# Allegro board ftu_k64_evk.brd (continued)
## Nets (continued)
WIFI/LCD_PWR_CNTL: R153.2 U1.136(PTD7/CMT_IRO/UART0_TX/FTM0_CH7/)
N16756265: R65.1 T1.10
N16756269: R66.1 T1.15
N16757442: D11.A(1) DN2.1 J16.2 R135.2
N16757516: D10.A(1) DN1.1 J16.3 R139.2
N16758787: C93.1 U28.1(C1+)
N16758791: C93.2 U28.3(C1-)
N16758795: C92.1 U28.4(C2+)
N16758815: C92.2 U28.5(C2-)
N16758819: C91.2 U28.6(V-)
N16758823: R135.1 U28.14(T1OUT)
N16758837: R134.2 U28.11(T1IN)
N16758843: R138.2 U28.12(R1OUT)
N16758849: C89.1 U28.2(V+)
N16758873: R139.1 U28.13(R1IN)
N16759319: R25.1 U5.7(H\O\L\D\)
N16772440: D3.A(C1) R27.1 R28.2 U6.1(VOUTA)
N16775214: D4.A(C1) R31.1 R33.2 U6.7(VOUTB)
N16775930: D5.A(C1) R38.1 R40.2 U6.8(VOUTC)
N16775968: R35.2 R37.2 U6.10(VINC+)
N16775998: R39.2 R40.1 U6.9(VINC-)
N16783367: C46.2 C47.1 R45.2 R47.1 U6.12(VIND+)
N16785222: C53.2 D17.A(C1) L8.1 PT3.3 R52.2 R53.2
N16785246: PT3.1 R50.2
N16785292: C49.1 D18.A(C1) L7.1 PT3.4 R51.1 R52.1
N16786136: L8.2 R54.1
N16786139: L7.2 R49.1
N16788483: D6.A(C1) R46.1 U6.13(VIND-) U6.14(VOUTD)
N16795804: D12.A(ANODE) R157.1
N16798051: C83.1 U17.5(CSLEW)
N16806806: C77.1 R96.1 Y2.1
N16812858: R2.2 U1.68(PTA16/CMP3_IN2/SPI0_SOUT/U\A\R\)
N16812861: R4.2 U1.69(PTA17/ADC1_SE17/SPI0_SIN/U\A\R\)
N16826797: R114.2 U21.2(R\E\) U21.3(DE) U22.4(COLLECTOR)
N16826898: R118.2 U21.4(DI) U23.4(COLLECTOR)
N16826947: J12.1 R124.1
N16841183: J14.1 R132.1
N16842812: R115.1 U22.2(CATHODE)
N16843774: R119.1 U23.2(CATHODE)
N16843986: R113.2 U19.2(CATHODE)
N16846359: R113.1 U21.1(RO)
N16848477: R125.1 U26.2(CATHODE)
N16848509: R123.2 U25.2(R\E\) U25.3(DE) U26.4(COLLECTOR)
N16848511: R131.1 U27.2(CATHODE)
N16848567: R130.2 U25.4(DI) U27.4(COLLECTOR)
N16848581: R121.2 U24.2(CATHODE)
N16848643: R121.1 U25.1(RO)
N16852593: R143.2 U29.8(W\D\O\)
N16852608: C95.1 J17.1 R142.2 SW3.3(B1) SW3.4(B2) U29.1(M\R\)
N16852627: R146.1 U29.7(R\E\S\E\T\)
N16852920: R147.1 U29.6(WDI)
N16858143: P1.11(LED1-) R67.1
N16858278: P1.9(LED2-) R68.1
N16861702: R92.1 T2.10
N16861704: R93.1 T2.15
N16871213: L20.1 L22.1 Q3.2(SOURCE) R149.1
N16871247: Q5.1(GATE) R153.1 R155.1
N16871250: C100.2 Q3.1(GATE) R149.2 R151.1
N16871668: Q5.3(DRAIN) R151.2
N16872241: Q6.1(GATE) R154.1 R156.1
N16872243: C102.2 Q4.1(GATE) R150.2 R152.1
N16872250: L21.1 L23.1 Q4.2(SOURCE) R150.1
N16872280: Q6.3(DRAIN) R152.2
N16877055: R159.2 U30.1(SHDN/RT)
N16877530: R160.2 U30.8(COMP)
N16877846: C111.1 R160.1
N16878286: L25.1 U30.3(LX)
N16878713: R158.1 R161.2 U30.7(FB)
N16899253: R97.1 U12.1(BGRES)
N16906260: P2.11(LED1-) R94.1
N16913941: R84.2 U12.31(SD8/GP1)
N16913953: R85.2 U12.29(SD9/GP2)
N16913968: R86.2 U12.28(SD10/GP3)
N16913982: R87.2 U12.27(SD11/GP4)
N16913996: R89.2 U12.26(SD12/GP5)
N16917794: R11.1 U1.74(R\E\S\E\T\)
N16918817: R12.1 U1.41(EXTAL32)
N16919212: R16.2 Y1.1(OE)
N16919504: R18.1 Y1.3(CLKOUT)
N16920348: R9.1 U1.19(USB0_DP)
N16920352: R10.1 U1.20(USB0_DM)
N16922932: D8.C(CATHODE) R99.1
N16922934: Q1.3(COLLECTOR) R99.2
N16922936: Q1.1(BASE) R101.1
N16922944: Q2.3(COLLECTOR) R100.2
N16922946: D9.C(CATHODE) R100.1
N16922998: R106.1 U15.2(CATHODE)
N16923008: J8.2 R104.2 U15.4(COLLECTOR)
N16923020: J8.1 R108.1 U15.3(EMITTER)
N16923032: R105.1 U16.2(CATHODE)
N16923042: J9.2 R103.2 U16.4(COLLECTOR)
N16923054: J9.1 R107.1 U16.3(EMITTER)
N16932299: PT2.1 R41.2
N16932357: R42.2 R44.1
N16935752: C38.2 CT2.2 D14.A(C1) L6.1 R32.2
N16935822: C35.1 CT2.1 D13.A(C1) L5.1 R30.1
N16935990: L6.2 R34.1
N16935992: L5.2 R29.1
N16963015: R89.1 TP12.1(PIN1)
N16963035: R84.1 TP9.1(PIN1)
N16963490: R85.1 TP10.1(PIN1)
N16963499: R86.1 TP8.1(PIN1)
N16963508: R87.1 TP11.1(PIN1)
N16964483: J17.2 R143.1
N16992640: R13.2 U1.3(PTE2/ADC1_SE6A/SPI1_SCK/U\A\R\T)
N16997663: R140.2 U28.9(R2OUT)
N16997666: R136.2 U28.10(T2IN)
N17002202: J10.15 TP18.1(PIN1)
N17002209: J10.14 TP17.1(PIN1)
N17002232: J10.16 TP19.1(PIN1)
N17002285: J22.11 TP27.1(PIN1)
N17002298: J22.13 TP28.1(PIN1)
N17002307: J22.15 TP30.1(PIN1)
N17009409: D7.A(C1) R55.1 U7.7(OUT1)
N17012939: R137.1 U28.7(T2OUT)
N17012953: R141.1 U28.8(R2IN)
N17025356: L15.1 U20.4(VOUT)
N17038152: R14.1 U2.8(SCL)
N17038155: R15.1 U2.7(SDA)
N17041648: J21.16 TP31.1(PIN1)
N17041650: J21.14 TP29.1(PIN1)
N17041652: J21.10 TP26.1(PIN1)
N17041654: J21.2 TP25.1(PIN1)
N17042189: J22.16 R148.1
N17042264: J22.17 TP34.1(PIN1)
N17042273: J22.19 TP35.1(PIN1)
N17042288: J22.18 TP36.1(PIN1)
N17042303: J22.20 TP37.1(PIN1)
N17042405: J21.18 TP38.1(PIN1)
N17042414: J21.20 TP39.1(PIN1)
N17045351: J10.17 TP40.1(PIN1)
N17045355: J10.19 TP41.1(PIN1)
N17045369: J10.18 TP42.1(PIN1)
N17045378: J10.20 TP43.1(PIN1)
N17061950: Q2.1(BASE) R102.1
N17108951: C65.1 R65.2 R66.2
N17109053: C76.1 R92.2 R93.2
N17166355: C125.1 R75.1 R76.1
N17166431: C126.1 R77.1 R78.1
N17167419: J10.13 TP45.1(PIN1)
N17171737: TP46.1(PIN1) U1.38(DAC0_OUT/ADC0_SE23/CMP1_IN3)
N17171740: TP47.1(PIN1) U1.39(DAC1_OUT/ADC1_SE23/CMP2_IN3)
N17171751: TP48.1(PIN1) U1.35(ADC1_SE16/ADC0_SE22/CMP2_IN2)
N17171755: TP49.1(PIN1) U1.26(ADC3_DM0/ADC2_DM3/ADC1_DM1)
N167792300: PT1.1 R36.2

Pads without a net: DN1 3; DN2 3; J1 1 2; J2 1 2; J16 1 4 6 7 8 9; J18 2 3 5 11 13 17 19; NOREF#5 1; NOREF#40 1; NOREF#42 1; P1 4 5 7 8; P2 4 5 7 8; R90 1; SS1 1; T1 4 5 12 13; T2 4 5 12 13; U1 28; U2 1 3 4; U3 28; U4 1; U7 3 4 6; U10 5; U11 4; U12 19 46; U14 5; U17 4; U18 3 4; U29 5

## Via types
v1: diameter 0.61, hole 0.305, TOP to BOTTOM, 540 vias
v2: diameter 0.787, hole 0.356, TOP to BOTTOM, 2 vias

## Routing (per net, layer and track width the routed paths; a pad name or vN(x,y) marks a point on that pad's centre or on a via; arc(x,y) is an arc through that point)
AGND: length 18.3
  TOP w0.508: TVS3.2 v1(18.31,142.98) ; L18.2 v1(65.88,140.82) ; TVS5.2 v1(46.16,143.3) ; R107.2 66.15,156.96 v1(65.88,157.23) ; U21.5 v1(32.82,129.81) ; R127.1 v1(48.37,137.2) ; TVS4.1 v1(48.9,143.24) ; C88.2 v1(45.19,136.06) ; C85.2 v1(29.19,136.39) ; U25.5 v1(52.06,132.11) ; C87.1 v1(64.94,129.01) ; TVS2.1 v1(20.52,142.93) ; R117.1 v1(30.87,136.46) ; R108.2 v1(55.28,157.44)
GND: length 199.4
  TOP w0.305: U1.6 65.49,68.25 v1(65.65,68.1) ; U1.93 84.62,63.25 v1(84.42,63.45) ; U1.71 v1(83.38,52.6) ; U1.134 v1(71.38,71.54) ; v1(68.88,49.81) 68.88,46.86 69.29,46.46 C6.2 ; U1.57 76.38,52.38 v1(76.55,52.55) ; U1.107 84.9,70.25 v1(84.63,69.98) ; C20.2 63.22,42.08 63.22,45.24 v1(63.73,45.75) 66.73,48.74 v1(67.16,48.74) ; U12.5 115.11,90.37 v1(115.29,90.55) 114.96,90.87 U12.6 ; U1.44 69.88,52.42 v1(69.69,52.6) ; v1(112.42,88.24) 112.14,87.96 U12.47 ; v1(63.22,62.51) 63.46,62.75 U1.17 ; v1(108.5,88.52) 109.14,87.89 U12.41 ; U12.45 v1(111.14,88.26) ; U12.48 v1(112.64,85.62) ; v1(65.86,62.48) 65.62,62.25 U1.18 ; U1.121 v1(77.88,71.54) ; U12.33 v1(106.96,89.87) ; U12.15 v1(111.64,94.07)
  TOP w0.381: U28.15 v1(132.64,38.41)
  TOP w0.406: C106.2 v1(137.43,137.41)
  TOP w0.508: U4.3 90.79,102.43 v1(90.39,102.03) ; C64.2 114.35,72.47 v1(114.57,72.69) ; U18.2 v1(142.26,120.29) ; C22.2 v1(107.64,33.35) ; C28.2 v1(72.68,95.49) ; C101.2 v1(122.02,134.03) ; v1(112.67,130.99) 112.34,130.66 Q6.2 ; v1(138.92,112.23) C80.2 v1(138.92,114.82) ; v1(98.55,75.77) 98.22,75.44 Q2.2 ; C69.2 v1(107.79,79.61) ; C29.2 v1(93.63,94.6) ; v1(86.91,96.19) 87.15,96.43 U3.34 ; R26.1 v1(93.85,144.91) ; C70.2 v1(106.24,102.24) ; C82.2 v1(130.82,106.08) ; v1(51.94,86.46) U31.1 v1(51.94,89.87) ; C5.2 v1(58.8,70.18) ; R159.1 v1(117.3,117.82) ; v1(57.75,62.18) 58.14,62.18 C17.2 ; C18.2 v1(58.03,60.76) ; C19.2 v1(56.81,60.86) ; C95.2 v1(127.21,20.31) ; C75.2 v1(119.68,86.16) ; C72.2 118.67,93.13 C73.2 v1(119.68,93.12) ; DN2.2 v1(146.72,44.72) ; C81.2 v1(139.88,111.09) ; C104.2 v1(128.77,138.71) ; U9.2 v1(122.93,65.74) ; C126.2 v1(120.73,86.57) ; C110.2 v1(108.14,121.24) ; C78.2 v1(109.34,79.48) ; C3.2 v1(70.33,77.29) ; C2.2 v1(76.55,77.29) ; v1(57.73,65.53) 58.01,65.81 C7.2 ; R73.2 v1(119.48,69.16) ; U2.5 v1(112.6,39.59) ; R72.1 v1(149.8,10.44) ; C62.2 v1(105,65.18) ; U10.2 v1(139.43,65.7) ; C111.2 v1(121.18,118.34) ; C9.2 v1(76.27,45.31) ; C125.2 v1(120.49,94.06) ; v1(90.14,69.16) 90.44,69.47 C1.2 90.47,70.03 C8.2 v1(90.47,72.31) ; TP_GND6.1 v1(54.53,77.39) ; C31.2 v1(76.52,141.2) ; DN1.2 v1(147.51,32.36) ; C97.2 v1(115.95,20.55) ; C105.2 v1(128.74,140.33) ; C24.2 v1(100.4,51.82) ; C86.1 v1(68.85,132.03) ; C99.2 v1(101.24,140.31) ; Y1.2 v1(92.73,42.72) ; C113.2 v1(58.99,93.99) ; U3.12 76.03,95.64 v1(75.84,95.45) ; v1(145.87,21.77) 145.87,22.81 D10.C 144.57,22.68 v1(144.57,21.92) ; U17.2 v1(132.65,108.45) ; v1(100.46,44.03) BT1.1 v1(100.46,40.93) ; C63.2 v1(117.93,58.59) ; C77.2 v1(120.14,81.73) ; C89.2 v1(129.93,42.28) ; C98.2 v1(98.73,140.28) ; v1(143.35,35.13) D11.C v1(146.81,35.13) ; SW3.1 v1(130.28,16.73) ; C68.2 v1(109.46,72.56) ; C61.2 v1(119.46,58.64) ; R74.1 104.92,62.36 v1(104.72,62.15) ; C25.2 v1(98.72,51.74) ; C90.2 v1(132.47,42.3) ; TP_GND5.1 v1(93.6,107.67) ; R67.2 v1(137.37,58.08) ; L2.2 v1(30.6,102.87) ; v1(57.94,95.75) C114.2 v1(57.94,98.54) ; C67.2 v1(111.02,72.59) ; TP_GND7.1 v1(141.71,127.25) ; C26.2 v1(87.55,49.23) ; U5.4 v1(87.93,147.17) ; C27.2 98.75,47.78 v1(98.19,48.34) ; C10.2 v1(84.2,45.67) ; TP_GND8.1 v1(132.92,52.68) ; R88.1 v1(110.52,102.4) ; SW3.2 v1(130.28,7.72) ; C60.2 v1(115.92,72.67) ; C96.2 v1(127.24,22.16) ; SW1.2 v1(137.28,7.8) ; C20.2 v1(63.8,40.66) 64.25,40.21 67.92,40.21 68.57,40.86 C21.2 69.29,41.53 v1(69.7,41.94) 69.84,42.08 v1(69.84,45.44) C6.2 ; SW2.2 v1(144.32,7.85) ; C112.2 v1(59.24,85.71) ; Q5.2 v1(96.94,129.35) ; C66.1 v1(148.62,13.14) ; C91.1 v1(121.64,36.09) ; R161.1 v1(124.87,115.31) ; C74.2 v1(119.71,84.74) ; v1(104.16,75.64) 103.86,75.35 Q1.2 ; L18.1 v1(69.34,140.82) ; C4.2 v1(90.62,64.72) ; v1(99.74,91.44) 99.99,91.69 C71.2 ; C115.2 v1(50.05,95.92) ; U14.2 v1(139.03,92.86) ; C107.2 v1(125.33,111.77) ; C108.2 v1(125.27,109.91) ; C116.2 v1(50.03,99.31) ; R94.2 v1(138.62,86.17) ; C30.2 93.41,96.17 v1(93.82,95.76) ; U13.2 v1(123.21,92.99) ; C84.2 v1(130.74,115.63) ; R156.2 v1(113.09,127.57) ; SW1.1 v1(137.28,16.84) ; R155.2 v1(95.69,126.48) ; C23.2 v1(111.93,46.1) ; R97.2 v1(119.77,83.32) ; U29.3 v1(121.8,22.6) ; D12.C v1(131.13,134.7) ; U29.4 v1(121.7,23.87) ; SW2.1 v1(144.32,16.76) ; C109.2 v1(109.85,117.73)
  vias: v1(56.29,62.26) v1(56.36,65.23) v1(112.08,66.12) v1(112.06,64.36) v1(113.91,66.19) v1(113.89,64.21) v1(115.23,110.19) v1(116.17,110.21) v1(117.29,110.21) v1(132.1,149.25) v1(133.52,149.15) v1(136.93,119.33) v1(136.98,116.43) v1(137.23,149.07) v1(138.42,149.07) v1(140.58,145.67) v1(141.65,145.67)
GNDA: length 63.2
  TOP w0.305: U1.34 63.45,54.25 v1(63.24,54.46) 63.53,54.75 U1.33
  TOP w0.381: U7.5 v1(56.39,5.34)
  TOP w0.508: C32.2 v1(44.37,61.14) ; C59.2 v1(45.21,24.36) ; C48.2 v1(51.66,39.12) ; C58.2 v1(42.6,25.39) ; C39.2 37.36,61.93 v1(37.66,62.23) ; C38.1 v1(13.88,116.6) ; U32.4 v1(50.79,17.71) ; C12.2 60.35,45.06 v1(60.37,45.03) ; C57.2 46.99,22.78 v1(46.32,23.44) ; v1(55.93,35.79) TVS1.1 v1(55.93,32.63) ; C45.1 37.86,50.15 v1(38.15,50.44) ; C40.1 v1(19.86,117.7) ; D7.C v1(60.33,5.58) ; U8.1 47.13,24.9 v1(46.48,25.55) ; D16.C v1(32.99,44.53) ; C118.2 v1(42.82,10.6) ; U6.11 v1(44.27,51.64) ; v1(56.8,8.08) 57.72,8.08 C55.2 ; C54.1 v1(38.2,27.63) ; C34.2 v1(46.96,60.48) ; C13.2 v1(61.39,49.25) ; D18.C v1(26.42,34.95) ; C42.2 v1(36.09,35.36) ; L2.1 v1(30.6,99.44) ; D6.C v1(53.69,38.48) ; D15.C v1(31.89,65.77) ; C16.2 v1(57.86,54.1) ; v1(51.07,64.22) 51.75,63.54 D3.C ; C56.2 v1(51.92,25.13) ; C33.2 v1(42.81,61.02) ; C122.2 v1(41.99,14.63) ; C119.2 v1(42.09,16.48) ; D13.C v1(19.98,102.66) ; C49.2 v1(22.8,34.3) ; C47.2 v1(47.43,45.81) ; C11.2 v1(60.4,48.41) ; R163.2 v1(52.86,19.86) ; C124.2 v1(57.31,16.59) ; D5.C v1(38.77,38.51) ; D4.C v1(41.52,61.19) ; U8.2 v1(48.08,25.68) ; C43.2 v1(38.89,56.65) ; C121.2 v1(57.1,13.44) ; C53.1 v1(32.52,10.03) ; C50.2 v1(36.29,27.66) ; C120.2 v1(57.21,14.99) ; C36.2 v1(19.89,98.84) ; C117.2 v1(41.92,13.08) ; R47.2 46.16,43.72 v1(46.35,43.92) ; D17.C v1(23.6,9.93) ; C35.2 v1(14.88,98.55) ; C14.2 v1(61.31,50.8) ; D14.C v1(19.88,112.6) ; C15.2 v1(57.81,55.63)
  vias: v1(34.11,54.31) v1(34.16,51.61) v1(51.33,57.33) v1(53.01,57.3) v1(53.51,59.61) v1(55.21,55.55)
GPRS_3V3/5V: length 31.9
  TOP w0.762: C101.1 117.32,133.8 Q4.3 116.78,130.9 C102.1
  TOP w1.016: C101.1 116.69,134.44 116.69,146.33 121.58,151.23 121.58,153.59 J22.1 J22.3
P3V3_LICELL: length 9.1
  TOP w0.635: BT1.2 98.96,44.03 98.75,44.25 C27.1
  TOP w0.762: C27.1 98.97,45.86 R17.1 100.72,45.49 D2.A
VBAT: length 80.3
  TOP w0.305: U1.42 68.88,55.01 v1(69.67,55.8)
  TOP w0.508: C23.1 111.93,42.85 111.33,42.25 U2.6
  TOP w0.762: C25.1 98.75,49.43 C24.1 ; D1.C 104.8,49.63 v1(105.43,50.27) ; D1.C 102.08,49.63 101.87,49.43 C24.1 ; D1.C D2.C ; C23.1 113.08,43.56 113.81,44.3 113.81,47.8 v1(107.8,53.81) 106.47,55.14 103.03,55.14 v1(98.58,59.59) ; R17.2 100.4,47.51 C24.1
  BOTTOM w0.762: v1(98.58,59.59) 97.21,60.96 74.82,60.96 v1(69.67,55.8) ; v1(107.8,53.81) 105.43,51.44 v1(105.43,50.27)
VCC_3V3: length 1.9
  TOP w0.508: v1(47.62,94.94) L4.2 v1(47.62,93.06)
  vias: v1(51.53,93.75) v1(51.58,94.95)
VDD_3V3: length 140.3
  TOP w0.305: U1.5 60.58,68.75 C5.1 ; U1.122 77.38,73.75 77.54,73.91 C2.1 ; U1.135 70.88,74.01 71.17,74.3 C3.1 ; C8.1 87.88,71.53 87.1,70.75 U1.108 ; C9.1 76.27,49.12 75.88,49.52 U1.56 ; U11.9 109.77,65.43 109.11,64.77 107.96,64.77 C62.1 ; C6.1 69.84,50.09 69.38,50.56 U1.43 ; C69.1 108.48,82.7 108.48,83.67 109.64,84.83 U12.42 ; U1.94 89.2,63.75 C4.1
  TOP w0.406: U12.30 102.54,91.37 C71.1 ; U1.16 62.79,63.25 60.23,65.81 ; U3.11 74.06,96.43 C28.1 ; U1.70 82.88,50.29 84.2,48.97 C10.1 v1(83.46,48.18) ; v1(91.79,56.08) 91.49,56.39 R7.1 ; C70.1 106.24,98.37 107.64,96.98 U12.23 ; R120.2 v1(41.04,107.26) ; R8.1 v1(90.74,54.14) ; v1(88.62,49.28) 88.92,48.97 C26.1 ; R112.2 v1(22.73,107.87) ; C6.1 v1(70.81,47.83) ; D1.A v1(102.89,52.17)
  TOP w0.508: D9.A v1(99.16,80.14) ; R1.1 v1(74.44,45.24) ; v1(143.08,100.43) 144.96,98.55 144.96,95.59 P2.10 ; C28.1 v1(74.05,95.52) ; R6.1 R5.1 v1(91.79,59.18) ; C3.1 v1(70.28,75.92) ; R82.2 99.86,98.74 v1(99.51,98.4) ; v1(103.27,92.18) 102.71,92.18 C71.1 ; R81.2 v1(109.11,102.26) ; v1(75.33,48.26) 75.71,47.88 C9.1 ; C4.1 v1(89.25,64.74) ; R71.1 111.48,59 v1(111.15,59.33) ; v1(105.4,98.63) 105.4,98.96 C70.1 ; L20.2 v1(104.87,127.53) ; R110.1 v1(142.39,17.88) ; v1(61.39,65.81) C7.1 ; R25.2 75.62,143.73 v1(75.25,143.36) ; U29.2 125.85,21.33 C96.1 v1(125.86,22.23) ; C5.1 v1(60.17,70.13) ; v1(133.84,42.33) C90.1 133.84,40.4 134.28,39.96 U28.16 ; R80.2 v1(113.27,102.5) ; v1(108.66,65.91) 107.92,65.18 C62.1 ; R24.2 v1(92.62,143.73) ; v1(104.31,81.05) 104.06,80.8 D8.A ; U5.8 78.08,142.37 C31.1 v1(77.89,141.23) ; C1.1 88.18,70 v1(87.93,70.26) ; R57.2 v1(105.09,69.46) ; U3.33 89.75,95.64 90.79,94.6 C29.1 v1(91.41,95.4) 91.41,96.15 C30.1 90.72,96.17 v1(90.39,96.49) ; L21.2 v1(120.08,131.72) ; v1(89.56,72.49) 89.1,72.03 C8.1 ; R16.1 v1(87.57,46.51) ; R56.2 v1(105.06,66.64) ; R23.2 v1(92.77,147.61) ; U2.2 110.06,33.37 C22.1 v1(111.27,33.35) ; Y1.4 v1(88.83,46.11) ; R142.1 v1(128.42,17.73) ; C69.1 107.79,83.12 v1(107.56,83.34) ; R109.1 v1(135.38,17.6) ; R83.2 v1(99.58,88.53) ; v1(93.89,100.76) 93.89,100.45 U4.5 ; R158.2 v1(124.85,113.9) ; L11.1 v1(117.88,72.67) ; R144.1 v1(115.95,19.03) ; R58.2 v1(104.91,61) ; R145.1 v1(115.92,25.07) ; C2.1 v1(76.7,75.92) ; R111.1 v1(134.41,105.89) ; v1(47.57,88.39) L3.2 v1(47.57,90.45) ; R79.2 v1(111.91,102.39)
  vias: v1(102.66,114.6) v1(102.66,113.33) v1(102.66,112.37) v1(102.69,111.25)
VDD_5V: length 75.5
  TOP w1.016: v1(54.6,66.98) 55.09,66.49 55.09,59.46 55.98,58.57 C19.1 58.71,58.57 R3.2 ; v1(54.66,71.02) 54.66,71.75 61.37,78.46 61.37,87.9 60.48,88.79 C112.1
  BOTTOM w1.016: v1(54.66,71.02) 54.6,70.97 v1(54.6,66.98)
  BOTTOM w1.524: v1(70.56,126.9) v1(71.65,127.99) 76.3,132.64 v2(103.96,132.64) v1(105.69,132.64)
VDDA_2V5: length 53.3
  TOP w0.305: C73.1 116.55,92.37 U12.9 ; U12.2 114.98,88.87 115.21,88.65 115.21,87.83 116.4,86.64 116.82,86.64 C75.1
  TOP w0.508: v1(125.57,89.53) 125.58,89.55 125.58,92.78 125.37,92.99 U13.5
  TOP w0.762: v1(116.14,84.74) C74.1 117.32,86.14 C75.1 ; v1(128.44,95.86) 128.42,95.89 T2.2 ; T2.7 v1(125.57,89.53) ; C73.1 117.3,93.13 C72.1 117.3,95.18 118,95.89 v1(118.82,95.89)
  BOTTOM w0.762: v1(116.14,84.74) 114.45,86.44 114.45,90.9 118.82,95.27 v1(118.82,95.89) 119.48,96.55 127.76,96.55 v1(128.44,95.86) 128.44,92.41 v1(125.57,89.53)
VDDA_3V3: length 25.6
  TOP w0.305: U1.31 60.37,55.75 C15.1
  TOP w0.508: v1(61.31,52.63) 61.08,52.4 L1.2 ; v1(61.21,54.1) C16.1 60.27,55.6 C15.1 ; U7.8 v1(55.35,8.19) ; U6.4 44.27,58.62 C32.1 v1(45.3,58.72) ; U8.3 49.03,23.07 C57.1 v1(49.99,22.78) ; v1(52.08,26.5) C56.1 50.23,27.24 U8.4 ; U32.8 45.07,13.9 C117.1 45.09,13.08 v1(45.5,12.67) ; C33.1 v1(42.81,57.74) ; C118.1 v1(45.45,11.56)
  vias: v1(36.85,65.94) v1(37.92,66.01) v1(38.93,66.04) v1(49.42,54.71) v1(49.47,55.91) v1(52.22,51.97) v1(53.08,52.78)
VDDCR_1.2V: length 4.9
  TOP w0.127: U11.6 111.79,69.39 C67.1 110.96,70.21 C68.1
WIFI/LCD_3V3/5V: length 35.9
  TOP w1.016: J21.1 J21.3 J21.5 ; C100.1 99.37,132.13 Q3.3 101.4,135.27 C99.1 98.73,135.43 C98.1 98.71,135.41 98.22,135.41 v2(96.93,136.7)
  BOTTOM w1.016: v2(96.93,136.7) 96.93,150.41 J21.1
ADC_S1: length 12.5
  TOP w0.127: TP4.1 91.99,53.62 89.3,53.62 87.93,54.99 87.93,55.27 86.45,56.75 U1.80
ADC_S2: length 11.5
  TOP w0.127: U1.79 86.45,56.25 87.55,55.15 87.55,55.01 89.19,53.37 93.87,53.37 TP3.1
ADC_S3: length 10.9
  TOP w0.127: TP2.1 94.91,53.11 89.09,53.11 86.45,55.75 U1.78
ADC_S4: length 11.7
  TOP w0.127: TP1.1 92.7,52.86 88.84,52.86 86.45,55.25 U1.77
DC_A1_OUT: length 53
  TOP w0.305: U1.59 77.38,49.98 v1(77.4,49.96) ; R55.2 59.39,7.78 C55.1 59.25,8.08 v1(59.25,8.94)
  BOTTOM w0.305: v1(59.25,8.94) 78.05,27.74 78.05,49.35 77.44,49.96 v1(77.4,49.96)
DC_IN: length 8.5
  TOP w0.508: J6.1 44.92,9.54 R48.1 49.78,7.33 49.78,7.29 U7.1
DC_OUT: length 8.4
  TOP w0.508: U7.2 50.05,6.64 48.07,4.66 R48.2 44.92,4.66 J6.2
DC_V1_OUT: length 32.8
  TOP w0.305: R46.2 51.66,43.56 ; 51.66,43.56 51.84,43.74 v1(52.8,43.74) ; 51.66,43.56 C48.1 ; v1(77.44,49.1) 78.01,49.67 78.01,50.21 77.88,50.34 U1.60
  BOTTOM w0.305: v1(52.8,43.74) 72.08,43.74 v1(77.44,49.1)
DEBUG_RX: length 113.1
  TOP w0.127: R138.1 140.25,33.86 v1(140.08,34.04) ; U1.51 73.38,50.4 73.13,50.15 73.13,20.4 80.58,12.95 106.67,12.95 v1(106.93,12.69)
  BOTTOM w0.127: v1(106.93,12.69) 107.28,12.69 109.12,14.53 123.99,14.53 140.08,30.61 v1(140.08,34.04)
DEBUG_TX: length 111.5
  TOP w0.127: v1(107.9,12.57) 107.87,12.57 107.24,13.21 80.69,13.21 73.41,20.49 73.41,49.56 73.88,50.03 U1.52 ; v1(141.35,31.52) 141.25,31.62 140.3,31.62 R134.1
  BOTTOM w0.127: v1(107.9,12.57) 107.9,12.95 109,14.05 123.87,14.05 v1(141.35,31.52)
DM9000_INT#: length 40
  TOP w0.127: U1.137 69.88,71.21 70.89,70.21 73.76,70.21 v1(74.01,70.46) ; v1(100.3,86.25) 100.27,86.27 100.27,86.83 R95.2
  BOTTOM w0.127: v1(100.3,86.25) 99.68,86.25 86.4,72.97 76.63,72.97 74.11,70.46 v1(74.01,70.46)
DM9000_WAKE: length 99.2
  TOP w0.127: R91.1 107.75,102.56 107.29,103.02 101.02,103.02 97.54,99.54 97.54,90.78 v1(97.79,90.53) ; v1(87.25,51.13) 87.25,51.83 U1.73 ; v1(97.26,88.67) 97.03,88.44 97.03,85.04 98.27,83.79 v1(104.17,83.79)
  BOTTOM w0.127: v1(97.79,90.53) 97.79,89.2 v1(97.26,88.67) ; v1(87.25,51.13) 89.61,51.13 91.25,49.49 106.99,49.49 112.86,55.36 112.86,66.89 111.63,68.12 111.63,73.3 105.99,78.94 105.99,81.97 v1(104.17,83.79)
DM_INT: length 5.2
  TOP w0.127: R95.1 102.22,87.18 R83.1 103.34,88.53 104.17,89.37 U12.34
DM_LED1: length 69.5
  TOP w0.127: P2.9 148.46,94.38 148.46,85.32 147.11,83.97 145.92,83.97 137.61,75.67 108.81,75.67 105.25,79.22 105.25,82.97 108.14,85.85 U12.39
DM_LED2: length 54.9
  TOP w0.127: U12.38 107.64,85.71 105,83.07 105,79.12 108.7,75.41 139.09,75.41 P2.12
EECLK: length 7.5
  TOP w0.127: R80.1 112.27,98.76 110,98.76 109.14,97.89 U12.20
EECS: length 6.7
  TOP w0.127: R79.1 111.17,99.01 109.54,99.01 108.64,98.1 U12.21
ENET1_RX+: length 26.5
  TOP w0.127: U11.23 116.01,65.93 v1(116.44,66.36) 116.95,66.87 R59.2 ; T1.6 127.5,63.65 128.14,63.02 128.14,62.56 128.8,61.9 128.8,60.31 128.08,59.59 125.22,59.59 123.01,61.8 123.01,64.66 122.88,64.79 U9.3 121.83,64.27 122.09,64.01 v1(122.22,64.01)
  BOTTOM w0.127: v1(122.22,64.01) 121.8,64.01 119.62,66.19 116.61,66.19 v1(116.44,66.36)
ENET1_RX-: length 26.5
  TOP w0.127: v1(123.77,63.86) 124.18,63.86 124.47,64.15 U9.4 123.41,64.79 123.29,64.66 123.29,61.91 125.33,59.87 127.96,59.87 128.52,60.43 128.52,61.77 128.38,61.91 128.12,61.91 127.99,61.77 127.99,61.57 127.53,61.11 T1.8 ; U11.22 116.2,65.43 116.29,65.52 v1(116.58,65.52) R60.2
  BOTTOM w0.127: v1(123.77,63.86) 123.4,63.49 121.93,63.49 119.5,65.91 116.97,65.91 v1(116.58,65.52)
ENET1_TX+: length 25.3
  TOP w0.127: R61.2 117.56,63.91 116.94,63.91 v1(116.47,64.38) 116.06,64.38 115.51,64.93 U11.21 ; v1(122.04,67.44) 121.83,67.22 U9.1 122.88,66.69 123.01,66.81 123.01,68.39 123.4,68.78 125.67,68.78 125.95,69.06 125.95,69.6 126.36,70 T1.1
  BOTTOM w0.127: v1(116.47,64.38) 116.13,64.38 115.79,64.71 115.79,67.18 116.89,68.28 123.03,68.28 123.24,68.07 123.24,67.46 122.96,67.18 122.3,67.18 v1(122.04,67.44)
ENET1_TX-: length 25.5
  TOP w0.127: R62.2 117.18,63.51 v1(116.36,63.51) 115.45,64.43 U11.20 ; v1(124.23,67.49) 124.47,67.25 U9.6 123.41,66.69 123.29,66.81 123.29,68.28 123.51,68.5 125.55,68.5 126.59,67.46 T1.3
  BOTTOM w0.127: v1(124.23,67.49) 123.72,67.49 123.51,67.69 123.51,68.19 123.15,68.55 116.77,68.55 115.51,67.3 115.51,64.59 116.36,63.74 v1(116.36,63.51)
ENET2_RX+: length 29.5
  TOP w0.127: T2.6 127.48,90.81 128.19,90.09 128.19,89.65 128.91,88.93 128.91,86.94 128.3,86.33 124.47,86.33 123.08,87.72 123.08,91.8 122.84,92.04 U13.3 122,91.22 v1(122.37,90.86) ; R77.2 116.92,87.57 v1(116.07,88.42) 115.12,89.37 U12.3
  BOTTOM w0.127: v1(116.07,88.42) 116.35,88.7 119.77,88.7 121.93,90.86 v1(122.37,90.86)
ENET2_RX-: length 29.2
  TOP w0.127: R78.2 116.36,88.92 v1(116.07,89.2) 115.52,89.76 115.01,89.76 114.9,89.87 U12.4 ; T2.8 127.45,88.27 128.21,89.03 128.42,89.03 128.63,88.81 128.63,87.06 128.19,86.61 124.58,86.61 123.36,87.83 123.36,91.74 123.66,92.04 U13.4 124.65,91.53 v1(124.07,90.96)
  BOTTOM w0.127: v1(116.07,89.2) 116.3,88.98 119.65,88.98 122.05,91.38 123.65,91.38 v1(124.07,90.96)
ENET2_TX+: length 19.6
  TOP w0.127: U12.7 115.2,91.37 v1(116.1,90.47) 116.29,90.29 R75.2 ; T2.1 126.44,97.16 125.52,96.24 123.75,96.24 123.18,95.67 123.18,94.07 123.06,93.94 U13.1 v1(122,94.75)
  BOTTOM w0.127: v1(116.1,90.47) 120.62,95 121.76,95 v1(122,94.75)
ENET2_TX-: length 21.6
  TOP w0.127: T2.3 126.54,94.61 125.19,95.96 123.87,95.96 123.46,95.55 123.46,94.07 123.59,93.94 U13.6 124.65,94.78 v1(124.4,95.02) ; U12.8 115.18,91.87 115.72,91.34 v1(116.17,91.34) 116.95,91.34 R76.2
  BOTTOM w0.127: v1(116.17,91.34) 116.57,91.34 120.5,95.28 124.15,95.28 v1(124.4,95.02)
ENET_3V3A: length 110
  TOP w0.305: U11.1 114.29,68.99 114.35,69.05 C64.1 ; C63.1 117.4,61.03 116.45,61.98 116.45,62.47 U11.19
  TOP w0.508: U9.5 125.22,65.74 125.47,65.48 v1(125.47,62.76) 125.85,62.38 T1.7
  TOP w0.762: P1.10 146.31,67.74 142.23,71.82 130.36,71.82 129.31,70.76 129.31,69.14 v1(128.9,68.73) T1.2 ; v1(125.9,71.73) 121.48,71.73 119.97,70.22 ; 119.97,70.22 L11.2 117.85,70.19 C60.1 115.9,70.21 C64.1 ; 119.97,70.22 120.87,69.32 120.87,67.39 120.36,66.87 R59.1 119.43,66.86 R60.1 R61.1 119.48,64.13 R62.1 119.46,62.8 C61.1 C63.1 ; v1(124.23,74.63) 107.13,74.63 102.1,69.6 102.1,65.13 103.5,63.73 R70.2
  BOTTOM w0.762: v1(125.47,62.76) 126.28,62.76 128.9,65.38 v1(128.9,68.73) v1(125.9,71.73) 124.23,73.41 v1(124.23,74.63)
ETH1_RXN: length 36
  TOP w0.127: v1(138.6,63.86) 138.53,63.86 138.26,64.12 U10.3 139.54,64.75 139.75,64.54 139.75,63.66 140.43,62.98 141.36,62.98 141.88,62.46 141.88,60.63 140.89,59.64 134.77,59.64 133.88,60.53 133.88,61.62 134.11,61.85 134.39,61.85 135.12,61.11 T1.9
  BOTTOM w0.127: P1.6 150.37,61.9 141.38,61.9 140.22,63.07 140.22,64.43 139.9,64.74 138.45,64.74 138.26,64.55 138.26,64.12 138.53,63.86 v1(138.6,63.86)
ETH1_RXP: length 36
  TOP w0.127: T1.11 135.05,63.65 134.41,63.02 134.41,62.55 133.6,61.74 133.6,60.41 134.65,59.36 141,59.36 142.16,60.51 142.16,62.59 141.49,63.26 140.55,63.26 140.02,63.78 140.02,64.62 140.33,64.92 140.73,64.92 U10.4 140.9,64.05 v1(140.74,63.88)
  BOTTOM w0.127: P1.3 152.9,63.62 151.47,62.18 141.5,62.18 140.74,62.94 v1(140.74,63.88)
ETH1_TXN: length 34.5
  TOP w0.127: v1(140.87,67.46) 140.9,67.43 U10.6 139.87,66.65 139.59,66.93 139.59,67.75 140.04,68.2 141.82,68.2 142.36,68.74 142.36,69.99 141.36,70.99 134.19,70.99 133.7,70.5 133.7,69.35 134.01,69.04 134.3,69.04 134.39,68.96 134.39,68.28 135.2,67.46 T1.14
  BOTTOM w0.127: v1(140.87,67.46) 140.81,67.41 140.18,67.41 140,67.59 140,67.84 140.18,68.02 142.36,68.02 144.42,65.96 150.38,65.96 P1.2
ETH1_TXP: length 34.4
  TOP w0.127: T1.16 135.05,70 134.39,69.34 134.11,69.34 133.98,69.47 133.98,70.36 134.31,70.69 134.31,70.71 141.24,70.71 142.08,69.88 142.08,68.86 141.7,68.48 139.92,68.48 139.31,67.87 139.31,66.93 139.04,66.65 U10.1 138.26,67.3 v1(138.42,67.46)
  BOTTOM w0.127: P1.1 144.53,66.24 142.47,68.3 140.06,68.3 139.72,67.96 139.72,67.67 139.52,67.46 v1(138.42,67.46)
ETH2_RXN: length 34.3
  TOP w0.127: v1(138.01,91.2) U14.3 138.92,91.91 139.14,91.69 139.14,90.66 139.43,90.37 141.69,90.37 142.41,89.65 142.41,88.51 142.22,88.32 137.83,88.32 136.73,87.22 134.51,87.22 133.93,87.81 133.93,88.75 134.01,88.82 134.39,88.82 134.94,88.27 T2.9
  BOTTOM w0.127: v1(138.01,91.2) 138.9,91.2 139.95,90.14 148.41,90.14 149.42,89.13 150.13,89.13 P2.6
ETH2_RXP: length 38.9
  TOP w0.127: v1(140.65,91.25) U14.4 139.63,91.91 139.42,91.69 139.42,90.78 139.54,90.65 141.8,90.65 142.69,89.76 142.69,88.39 142.34,88.04 137.94,88.04 136.85,86.94 134.4,86.94 133.65,87.69 133.65,88.86 133.91,89.12 134.25,89.12 134.36,89.23 134.36,90.14 135.02,90.81 T2.11
  BOTTOM w0.127: P2.3 152.59,90.72 152.59,90.03 151.62,89.05 150.61,89.05 150.25,89.41 149.54,89.41 148.52,90.42 140.07,90.42 139.63,90.86 139.63,91.04 139.83,91.25 v1(140.65,91.25)
ETH2_TXN: length 30.9
  TOP w0.127: v1(139.67,94.42) 140.28,93.81 U14.6 140.76,93.81 142.03,95.08 142.03,96.76 140.65,98.15 134.07,98.15 133.7,97.78 133.7,97.01 134.27,96.44 134.27,95.16 134.82,94.61 T2.14
  BOTTOM w0.127: v1(139.67,94.42) 139.91,94.67 141.2,94.67 143.31,92.56 150.62,92.56 151.04,92.13 P2.2
ETH2_TXP: length 31.7
  TOP w0.127: U14.1 138.33,93.81 138.65,94.13 138.65,94.31 v1(138.87,94.52) 139.29,94.95 141.5,94.95 141.75,95.2 141.75,96.65 140.53,97.87 134.26,97.87 133.98,97.59 133.98,97.13 134.23,96.88 135.2,96.88 T2.16
  BOTTOM w0.127: v1(138.87,94.52) 139.29,94.95 141.32,94.95 143.43,92.84 150.57,92.84 150.88,93.15 P2.1
EXT_5V: length 60.1
  TOP w0.508: L17.1 v1(61.39,128.45)
  BOTTOM w0.508: v1(61.39,128.45) 61.39,145.41 54.2,152.6 26.38,152.6 J13.1
EXTAL: length 48.6
  TOP w0.127: v1(84.27,50.15) 84.27,50.32 83.88,50.71 U1.72 ; v1(112.31,68.17) 112.31,67.16 U11.5 ; R18.2 v1(90.53,49.24)
  BOTTOM w0.127: v1(112.31,68.17) 113.11,67.37 113.11,55.26 107.09,49.24 v1(90.53,49.24) 89.28,50.5 84.62,50.5 v1(84.27,50.15)
EZP_CS: length 3.5
  TOP w0.127: R1.2 74.44,49.07 74.88,49.51 U1.54
FB_AD0: length 56.9
  TOP w0.127: U4.2 92.33,101.96 91.6,101.23 U3.40 86.98,101.23 v1(86.94,101.27) ; U1.133 71.88,73.86 72.12,74.11 72.12,77.76 68.19,81.69 68.19,99.9 70.23,101.94 71.94,101.94 v1(72.46,101.42)
  BOTTOM w0.127: v1(86.94,101.27) 84.5,103.71 74.75,103.71 v1(72.46,101.42)
FB_AD0_N: length 3.2
  TOP w0.127: U3.39 90.78,100.43 U4.4
FB_AD1: length 84.5
  TOP w0.127: U12.32 104.64,90.37 103.75,89.48 99.54,89.48 98.96,88.91 98.15,88.91 97.1,89.97 97.1,103.34 95.38,105.05 79.12,105.05 v1(78.53,104.47) 78.49,104.43 U3.1 ; v1(71.52,101.42) 70.07,101.42 68.45,99.8 68.45,82.07 72.38,78.14 U1.132
  BOTTOM w0.127: v1(78.53,104.47) 74.57,104.47 v1(71.52,101.42)
FB_AD2: length 43.2
  TOP w0.127: v1(79.34,102.62) 79.29,102.62 78.28,103.63 U3.2 ; v1(69.87,100.48) 68.7,99.31 68.7,82.52 72.88,78.34 U1.131
  BOTTOM w0.127: v1(79.34,102.62) 78.85,103.11 75.7,103.11 73.21,100.62 70.01,100.62 v1(69.87,100.48)
FB_AD3: length 40.9
  TOP w0.127: v1(71.28,99.96) 69.76,99.96 68.96,99.16 68.96,82.97 73.38,78.55 U1.130 ; v1(78.58,102.59) 78.34,102.83 U3.3
  BOTTOM w0.127: v1(78.58,102.59) 75.84,102.59 73.02,99.77 71.47,99.77 v1(71.28,99.96)
FB_AD4: length 37.4
  TOP w0.127: v1(69.97,99.44) 69.21,98.68 69.21,83.43 73.88,78.76 U1.129 ; v1(75.89,101.9) 76.02,102.03 U3.4
  BOTTOM w0.127: v1(75.89,101.9) 73.43,99.44 v1(69.97,99.44)
FB_AD5: length 48
  TOP w0.127: v1(71.17,88.27) 70.73,88.7 70.73,97.22 74.74,101.23 U3.5 ; v1(74.37,88.28) 74.37,87.71 76.57,85.51 79.83,85.51 80.03,85.72 80.03,88.82 80.23,89.03 80.67,89.03 80.88,88.82 U1.115
  BOTTOM w0.127: v1(74.37,88.28) 74.35,88.27 v1(71.17,88.27)
FB_AD6: length 31.9
  TOP w0.127: U3.18 75.98,90.84 74.89,89.76 74.89,87.55 76.57,85.87 79.55,85.87 79.75,86.07 79.75,89.08 79.95,89.28 81.17,89.28 81.38,89.08 U1.114
FB_AD7: length 30.4
  TOP w0.127: U3.19 76.65,90.04 75.59,88.98 75.59,87.21 76.49,86.3 79.29,86.3 79.5,86.51 79.5,89.38 79.7,89.59 81.67,89.59 81.88,89.38 U1.113
FB_AD8: length 30.1
  TOP w0.127: U1.112 82.38,89.76 82.17,89.97 79.45,89.97 79.24,89.76 79.24,86.88 79.04,86.67 76.48,86.67 75.84,87.32 75.84,88.77 76.31,89.24 U3.20
FB_AD9: length 29.3
  TOP w0.127: U1.111 82.88,90.07 82.67,90.27 79.19,90.27 78.99,90.07 78.99,87.25 78.79,87.05 76.47,87.05 76.09,87.42 76.09,87.88 76.65,88.44 U3.21
FB_AD10: length 26.7
  TOP w0.127: U1.110 83.38,90.47 83.17,90.68 78.94,90.68 78.73,90.47 78.73,87.85 78.53,87.64 U3.22
FB_AD11: length 17.8
  TOP w0.127: U1.109 83.88,84.62 86.9,87.64 U3.23
FB_AD12: length 28.1
  TOP w0.127: U3.24 89.89,88.44 90.18,88.15 90.18,87.31 89.06,86.19 89.06,74.5 91.23,72.33 91.23,69.17 90.65,68.59 87.31,68.59 86.65,69.25 U1.105
FB_AD13: length 29.2
  TOP w0.127: U1.104 86.56,68.75 86.97,68.34 90.76,68.34 91.49,69.07 91.49,72.44 89.31,74.61 89.31,86.09 90.43,87.21 90.43,88.46 89.64,89.24 U3.25
FB_AD14: length 30.3
  TOP w0.127: U1.103 86.51,68.25 86.68,68.08 90.86,68.08 91.74,68.96 91.74,72.54 89.57,74.72 89.57,85.98 90.68,87.1 90.68,88.77 89.42,90.04 U3.26
FB_AD15: length 36.6
  TOP w0.127: U1.97 86.79,65.25 87.52,65.99 90.93,65.99 93.26,68.33 93.26,73.18 92.17,74.27 92.17,83.13 v1(92.55,83.52) ; v1(90.09,83.52) 90.09,85.52 91.21,86.64 91.21,89.26 89.62,90.84 U3.27
  BOTTOM w0.127: v1(90.09,83.52) v1(92.55,83.52)
FB_AD16: length 53.5
  TOP w0.127: U1.96 86.95,64.75 87.93,65.74 91.03,65.74 93.52,68.22 93.52,73.28 92.43,74.38 92.43,81.85 95.98,85.4 95.98,102.18 94.51,103.66 90.75,103.66 89.92,102.83 U3.42
FB_AD17: length 54.2
  TOP w0.127: U1.95 87.16,64.25 88.39,65.48 91.14,65.48 93.77,68.11 93.77,73.39 92.68,74.48 92.68,81.74 96.24,85.3 96.24,102.29 94.61,103.91 89.43,103.91 89.15,103.63 U3.43
FB_AD18: length 57.8
  TOP w0.127: U1.92 91.6,62.75 94.03,65.18 94.03,73.49 92.93,74.59 92.93,80.8 96.62,84.48 96.62,103.02 95.21,104.43 U3.44
FB_AD24: length 75.4
  TOP w0.127: v1(89.96,92.41) 89.92,92.44 U3.29 82.96,92.44 82.18,93.23 82.18,96.15 78.7,99.63 U3.7 73.5,99.63 70.99,97.12 70.99,89.29 78.38,81.9 U1.120 ; v1(109.66,96.79) 109.76,96.79 110.14,96.41 U12.18
  BOTTOM w0.127: v1(89.96,92.41) 90.94,93.38 95.02,93.38 98.43,96.79 v1(109.66,96.79)
FB_AD25: length 78.2
  TOP w0.127: v1(90.72,92.41) 90.72,92.58 90.06,93.24 U3.30 ; v1(82.57,92.02) 81.92,92.67 81.92,95.24 78.33,98.83 U3.8 73.06,98.83 71.24,97.01 71.24,89.4 78.88,81.76 U1.119 ; U12.17 110.64,96.64 v1(110.54,96.75)
  BOTTOM w0.127: v1(110.54,96.75) 110,96.22 98.22,96.22 95.13,93.13 91.45,93.13 v1(90.72,92.41) 90.11,91.8 82.8,91.8 v1(82.57,92.02)
FB_AD26: length 79.6
  TOP w0.127: v1(91.49,92.41) 89.85,94.04 U3.31 ; v1(81.81,92.05) 81.67,92.19 81.67,95.02 78.66,98.03 U3.9 72.62,98.03 71.5,96.9 71.5,89.5 79.38,81.62 U1.118 ; U12.16 111.14,96.31 111.3,96.47 v1(111.3,96.75)
  BOTTOM w0.127: v1(111.3,96.75) 110.38,95.83 98.37,95.83 95.42,92.88 91.96,92.88 v1(91.49,92.41) 90.37,91.29 82.57,91.29 v1(81.81,92.05)
FB_AD27: length 81.3
  TOP w0.127: U1.117 79.88,81.48 71.75,89.61 71.75,96.8 72.18,97.23 U3.10 78.99,97.23 81.05,95.17 v1(81.05,92.08) ; U3.32 89.78,94.84 92.25,92.38 v1(92.25,92.35) ; v1(112.26,96.75) 112.14,96.63 U12.14
  BOTTOM w0.127: v1(112.26,96.75) 110.87,95.35 98.42,95.35 95.42,92.35 v1(92.25,92.35) 90.77,90.88 82.24,90.88 81.05,92.07 v1(81.05,92.08)
FB_AD28: length 88
  TOP w0.127: U1.102 90.89,67.75 91.99,68.85 91.99,72.65 90.9,73.74 90.9,85.55 94.71,89.36 94.71,95.63 93.11,97.23 U3.35 86.89,97.23 v1(86.76,97.1) ; U3.13 78.76,94.84 v1(79.52,94.08) ; v1(114.32,96.9) 114.37,96.85 114.37,95.94 113.76,95.33 U12.13
  BOTTOM w0.127: v1(114.32,96.9) 111.98,99.24 90.93,99.24 88.79,97.1 v1(86.76,97.1) 81.71,97.1 79.52,94.92 v1(79.52,94.08)
FB_AD29: length 91
  TOP w0.127: v1(115.08,96.82) 115.08,94.07 114.88,93.87 U12.12 ; v1(78.73,94.04) U3.14 ; v1(86.99,97.94) 87.08,98.03 U3.36 90.15,98.03 90.51,97.68 93.53,97.68 94.97,96.24 94.97,89.25 91.16,85.44 91.16,73.85 92.25,72.75 92.25,68.75 90.75,67.25 U1.101
  BOTTOM w0.127: v1(115.08,96.82) 115.08,97.33 112.92,99.49 90.09,99.49 88.54,97.94 v1(86.99,97.94) 81.91,97.94 78.73,94.77 v1(78.73,94.04)
FB_AD30: length 96.8
  TOP w0.127: v1(87.02,98.78) 87.07,98.83 U3.37 89.71,98.83 90.61,97.93 93.64,97.93 95.22,96.35 95.22,89.15 91.41,85.34 91.41,73.95 92.5,72.86 92.5,68.64 90.61,66.75 U1.100 ; U12.11 115.09,93.37 115.83,94.11 115.83,96.73 v1(115.84,96.75) ; U3.15 75.86,93.24 v1(75.81,93.29)
  BOTTOM w0.127: v1(115.84,96.75) 115.84,97.13 113.22,99.75 88.29,99.75 87.32,98.78 v1(87.02,98.78) 81.3,98.78 v1(75.81,93.29)
FB_AD31: length 101.5
  TOP w0.127: U12.10 115.3,92.87 116.62,94.19 116.62,96.71 v1(116.6,96.72) ; v1(75.79,92.53) 75.88,92.44 U3.16 ; v1(86.99,99.57) 87.05,99.63 U3.38 89.69,99.63 91,98.32 93.6,98.32 95.47,96.45 95.47,89.04 91.66,85.23 91.66,74.06 92.76,72.97 92.76,68.54 90.72,66.5 87.06,66.5 86.81,66.25 U1.99
  BOTTOM w0.127: v1(75.79,92.53) 75.25,93.07 75.25,93.7 81.12,99.57 v1(86.99,99.57) 87.42,100 113.33,100 v1(116.6,96.72)
FB_CS0_N: length 36.3
  TOP w0.127: U3.6 75.94,100.43 v1(75.74,100.23) ; U1.128 74.38,73.6 74.13,73.84 74.13,79.21 69.46,83.88 69.46,98.17 69.87,98.58 v1(69.92,98.58)
  BOTTOM w0.127: v1(69.92,98.58) 70.52,99.19 74.7,99.19 v1(75.74,100.23)
FB_CS1_N: length 42.2
  TOP w0.127: U1.127 74.88,70.49 v1(74.82,70.43) ; v1(105.66,85.34) 106.4,85.34 107.14,86.08 U12.37
  BOTTOM w0.127: v1(74.82,70.43) 77.11,72.72 86.51,72.72 99.51,85.73 105.28,85.73 v1(105.66,85.34)
FB_OE_N: length 65.1
  TOP w0.127: U3.41 89.63,102.03 91,103.4 94.28,103.4 95.73,101.96 95.73,87.48 v1(94.46,86.21) 91.92,83.67 91.92,74.16 93.01,73.07 93.01,68.43 90.82,66.24 87.17,66.24 86.68,65.75 U1.98 ; v1(98.09,86.21) 98.57,85.73 102.05,85.73 103.53,87.2 103.53,87.43 104.97,88.87 U12.35
  BOTTOM w0.127: v1(98.09,86.21) v1(94.46,86.21)
FB_RW_N: length 64.7
  TOP w0.127: U1.116 80.38,84.72 80.22,84.88 79.98,84.88 79.78,84.67 79.78,82.72 79.6,82.55 79.36,82.55 79.19,82.72 79.19,84.88 78.99,85.08 78.68,85.08 78.48,84.88 78.48,84.02 78.28,83.82 78.09,83.82 77.9,84.01 77.9,84.88 77.7,85.08 76.64,85.08 73.85,87.87 73.85,90.13 75.37,91.64 U3.17 79.67,91.64 79.99,91.33 83.37,91.33 v1(86.43,88.27) ; U12.36 105.05,88.37 102.16,85.47 v1(97.66,85.47)
  BOTTOM w0.127: v1(97.66,85.47) 89.22,85.47 v1(86.43,88.27)
GP6: length 8.9
  TOP w0.127: TP13.1 102.19,100.2 R82.1 103.98,96.95 103.98,94.67 104.77,93.87 U12.25
GPIO_1: length 56.9
  TOP w0.127: v1(84.17,16.84) 83.73,17.28 83.73,19.41 85.64,21.32 85.64,51.96 84.22,53.38 84.22,59.66 84.81,60.25 U1.87
  BOTTOM w0.127: J10.3 81.31,13.98 v1(84.17,16.84)
GPIO_2: length 59.6
  TOP w0.127: v1(84.09,15.7) 83.34,16.45 83.34,19.38 85.39,21.43 85.39,51.85 83.97,53.27 83.97,59.84 84.88,60.75 U1.88
  BOTTOM w0.127: v1(84.09,15.7) 82.11,13.71 82.11,6.18 J10.4
GPIO_3: length 52.2
  TOP w0.127: v1(84.25,17.96) 84.25,19.35 86.41,21.51 86.41,51.55 84.55,53.41 84.55,54.41 84.9,54.75 U1.76
  BOTTOM w0.127: v1(84.25,17.96) 79.31,13.02 J10.5
GPIO_4: length 53
  TOP w0.127: J10.6 78.51,4.58 76.67,4.58 76.51,4.74 76.51,7.71 77.85,9.05 77.85,13.28 71.38,19.75 U1.47
GPIO_5: length 46.8
  TOP w0.127: J10.7 78.1,8.17 78.1,13.77 71.88,19.99 U1.48
GPIO_6: length 48.8
  TOP w0.127: U1.49 72.38,19.95 78.35,13.97 78.35,6.43 J10.8
GPIO_7: length 46
  TOP w0.127: v1(78.63,17.27) 77.36,18.54 77.36,48.03 76.88,48.52 U1.58
  BOTTOM w0.127: J10.9 75.31,13.95 v1(78.63,17.27)
GPIO_8: length 48.5
  TOP w0.127: U1.61 78.38,20.35 78.1,20.07 78.1,18.59 v1(78.63,18.06)
  BOTTOM w0.127: J10.10 74.29,6.4 74.29,13.72 v1(78.63,18.06)
GPIO_9: length 46.2
  TOP w0.127: U1.62 78.88,19.22 v1(78.62,18.96)
  BOTTOM w0.127: v1(78.62,18.96) 78.62,18.96 73.31,13.65 J10.11
GPIO_10: length 50.6
  TOP w0.127: v1(80.03,19.66) 79.38,20.31 U1.63
  BOTTOM w0.127: v1(80.03,19.66) 78.56,19.66 72.36,13.46 72.36,6.33 J10.12
GPIO_IN_1: length 94.7
  TOP w0.127: U1.85 87.52,59.25 88.89,60.63 102.46,60.63 103.96,59.13 107.79,59.13 115.79,51.13 115.79,27.83 117.29,26.33 130.8,26.33 132.76,24.37 R109.2 132.79,17.58 SW1.3 SW1.4
GPIO_IN_2: length 98.3
  TOP w0.127: U1.86 87.31,59.75 88.48,60.93 102.52,60.93 104.06,59.39 107.9,59.39 116.05,51.24 116.05,27.93 117.39,26.59 131.47,26.59 139.82,18.24 R110.2 139.83,17.88 SW2.3 SW2.4
GPIO_OUT_1: length 24
  TOP w0.127: R101.2 99.41,76.08 99.31,75.97 99.31,73.89 94.53,69.11 94.53,64.95 90.84,61.25 U1.89
GPIO_OUT_2: length 22.5
  TOP w0.127: R102.2 93.44,76.17 93.19,75.91 93.19,74.69 94.28,73.6 94.28,65.07 90.96,61.75 U1.90
GPIO_OUT_3: length 63.7
  TOP w0.127: U1.91 75.35,62.25 65.79,71.81 65.79,99.83 v1(65.45,100.18) ; R106.2 v1(58.86,107.26)
  BOTTOM w0.127: v1(58.86,107.26) 58.86,106.77 v1(65.45,100.18)
GPIO_OUT_4: length 43.3
  TOP w0.127: v1(66.05,101.14) 66.05,71.91 67.27,70.69 68.84,70.69 69.38,71.22 U1.138 ; R105.2 63.39,107.41 v1(63.37,107.39)
  BOTTOM w0.127: v1(63.37,107.39) 64.61,106.15 64.61,102.58 v1(66.05,101.14)
GPRS_CTS: length 111.6
  TOP w0.127: J22.6 115.12,154.05 113.53,154.05 113.08,153.59 113.08,146.2 110.13,143.26 98.28,143.26 85.75,130.72 85.75,117.36 75.2,106.82 75.2,103.13 69.72,97.64 69.72,84.72 74.85,79.59 74.85,74.77 75.38,74.24 U1.126
GPRS_DCD: length 110.7
  TOP w0.127: J22.10 111.94,153.18 111.94,149.46 107.32,144.85 97.83,144.85 91.68,138.7 81.77,138.7 78.84,135.77 78.84,111.98 67.18,100.32 67.18,78.2 67.88,77.5 U1.141
GPRS_DTR: length 114.2
  TOP w0.127: U1.140 68.38,77.71 67.43,78.65 67.43,100.22 79.09,111.88 79.09,135.67 81.62,138.2 91.89,138.2 98.04,144.35 108.44,144.35 112.82,148.73 112.82,154.35 J22.9
GPRS_PWR_CNTL: length 118.8
  TOP w0.127: v1(106.01,146.81) 105.97,146.85 R148.2 99.33,148.12 91.16,139.96 81.94,139.96 77.69,135.71 77.69,111.92 66.42,100.64 66.42,76.63 66.38,76.59 U1.144 ; v1(108.03,132.64) 108.03,131.42 R154.2
  BOTTOM w0.127: v1(106.01,146.81) 108.03,144.8 v1(108.03,132.64)
GPRS_RI: length 109.9
  TOP w0.127: J22.12 109.94,153.18 109.94,147.82 107.46,145.35 97.62,145.35 91.48,139.2 81.91,139.2 78.45,135.74 78.45,111.95 66.92,100.43 66.92,77.75 67.38,77.29 U1.142
GPRS_RST: length 108.1
  TOP w0.127: J22.14 107.94,153.18 107.94,147.82 105.96,145.85 97.42,145.85 91.27,139.7 82.05,139.7 77.95,135.6 77.95,111.81 66.67,100.54 66.67,77.29 66.88,77.08 U1.143
GPRS_RTS: length 108.1
  TOP w0.127: U1.125 75.88,74.1 75.1,74.87 75.1,79.7 69.97,84.83 69.97,97.54 75.46,103.02 75.46,106.71 86,117.25 86,130.61 98.39,143 110.23,143 113.96,146.73 J22.8
GPRS_RX: length 109.8
  TOP w0.127: J22.4 117.96,150.37 110.34,142.75 98.49,142.75 86.25,130.51 86.25,117.15 75.71,106.61 75.71,102.92 70.23,97.43 70.23,84.93 75.36,79.8 75.36,74.98 76.38,73.96 U1.124
GPRS_TX: length 110.6
  TOP w0.127: U1.123 76.88,73.81 75.61,75.08 75.61,79.91 70.48,85.04 70.48,97.33 75.97,102.81 75.97,106.5 86.51,117.04 86.51,130.4 98.6,142.49 110.45,142.49 119.96,152.01 J22.2
HOSTUSB_C_D_N: length 10.1
  TOP w0.127: U18.6 143.21,116.77 ; 143.21,116.77 143.21,116.86 142.29,117.78 140.23,117.78 139.88,117.43 L14.2 ; 143.21,116.77 143.36,116.77 144.11,117.53 147.22,117.53 J11.A2
HOSTUSB_C_D_P: length 10.1
  TOP w0.127: L14.3 139.91,118.23 140.1,118.03 142.33,118.03 143.21,118.91 ; 143.21,118.91 U18.1 ; 143.21,118.91 143.21,118.73 144.17,117.78 147.22,117.78 J11.A3
I1A_IN: length 80.5
  TOP w0.305: U6.2 46.81,58.79 R28.1 46.78,59.49 46.12,60.15 46.12,63.6 v1(43.2,66.52)
  BOTTOM w0.305: CT1.1 17.04,115.84 17.04,107.31 40.13,84.23 40.13,69.6 v1(43.2,66.52)
I1A_OUT: length 19.2
  TOP w0.305: C34.1 48.46,62.83 R27.2 48.8,62.87 49.8,61.87 52.8,61.87 v1(53.23,61.44) ; U1.25 v1(63.24,58.75)
  BOTTOM w0.305: v1(53.23,61.44) 55.92,58.75 v1(63.24,58.75)
I2A_N: length 86.2
  TOP w0.178: v1(19.37,108.81) 19.21,108.98 C37.2 18.28,114.95 R34.2 18.31,115.16 C40.2 ; U1.24 63.6,59.25 63.51,59.33 62.94,59.33 60.98,57.38 54.22,57.38 52.9,58.7 52.66,58.7 v1(52.6,58.76)
  BOTTOM w0.178: v1(52.6,58.76) 52.6,59.23 52.62,59.26 52.62,61.88 42.51,71.98 42.51,85.85 19.59,108.77 19.42,108.77 v1(19.37,108.81)
I2A_P: length 86.3
  TOP w0.178: v1(19.34,107.61) C37.1 18.28,105.31 18.46,105.13 18.46,102.16 18.25,101.95 R29.2 19.1,101.41 19.32,101.19 C36.1 ; v1(51.81,58.98) 52.14,59.31 52.83,59.31 54.35,57.78 60.83,57.78 62.79,59.75 U1.23
  BOTTOM w0.178: v1(19.34,107.61) 20.14,107.61 42.13,85.62 42.13,71.75 52.24,61.65 52.24,59.41 v1(51.81,58.98)
I2C_SCL: length 32.1
  TOP w0.127: R14.2 108.43,46.89 TP6.1 108.25,50.77 105.51,53.52 103.06,53.52 98.7,57.89 92.73,57.89 91.94,57.1 89.77,57.1 89.14,57.73 R6.2 88.67,58.25 U1.83
I2C_SDA: length 34.3
  TOP w0.127: R15.2 110.18,46.94 TP5.1 110.33,49.12 105.23,54.23 102.71,54.23 96.74,60.2 89.56,60.2 89.14,59.78 R5.2 88.71,58.75 U1.84
L_XIN: length 10.7
  TOP w0.127: U12.44 110.64,84.05 112.29,82.4 116.93,82.4 R96.2
L_XOUT: length 7.8
  TOP w0.127: Y2.2 109.9,82 C78.1 109.34,83.54 110.14,84.34 U12.43
LED3: length 6.2
  TOP w0.127: U12.24 105.79,95.33 104.7,96.41 R90.2
MODE0: length 5.3
  TOP w0.127: U11.8 110.32,65.93 109.61,66.64 R56.1 107.63,66.69 R63.2
MODE1: length 6.1
  TOP w0.127: U11.7 108.05,69.46 R57.1 107.63,69.48 R64.2
NORFLASH_WP: length 4.8
  TOP w0.127: U5.3 91.09,144.91 R26.2 91.09,146.39 R23.1
PHY_INT_B: length 2.7
  TOP w0.127: U11.14 112.29,60.8 R71.2
PHY_LED1: length 57.9
  TOP w0.127: P1.12 148.1,57.6 148.1,70.94 145.31,73.74 114.29,73.74 113.29,72.73 U11.3
PHY_LED2: length 31.5
  TOP w0.127: U11.2 113.79,67.89 113.54,68.14 113.54,72.63 114.4,73.48 138.02,73.48 R68.2
PHY_RST_B: length 2.9
  TOP w0.127: R69.2 112.79,61.31 U11.15
PWRST#: length 5.8
  TOP w0.127: R98.2 106,83 108.64,85.63 U12.40
RBIAS: length 3.6
  TOP w0.127: U11.24 115.14,66.43 116.96,68.25 R73.1
RESET_B: length 114.1
  TOP w0.127: v1(112.34,19.03) R144.2 113.36,19.76 113.55,19.95 C97.1 113.55,21.87 R146.2 108.27,21.98 94.91,35.34 v1(94.91,48.31) 94.91,48.77 93.47,50.22 R11.2 ; v1(106.55,79.17) 106,79.72 R98.1 ; R69.1 113.5,58.02 v1(113.91,57.61)
  BOTTOM w0.127: v1(106.55,79.17) 113.37,72.35 113.37,58.87 113.91,58.32 v1(113.91,57.61) 113.91,55.3 107.6,48.98 95.59,48.98 v1(94.91,48.31) ; J18.15 101.19,8.99 111.22,19.03 v1(112.34,19.03)
RMII0_CRS_DV: length 38.3
  TOP w0.127: v1(81.1,52.48) 80.88,52.26 U1.66 ; R58.1 108.11,61 v1(108.54,61.43) 108.96,61.85 108.96,63.2 110.19,64.43 U11.11
  BOTTOM w0.127: v1(108.54,61.43) 104.53,57.42 87.26,57.42 82.9,53.06 81.68,53.06 v1(81.1,52.48)
RMII0_MDC: length 30.9
  TOP w0.127: R7.2 88.36,56.39 v1(87.85,56.9) 87,57.75 U1.82 ; v1(109.72,61.21) 110.23,61.72 111.02,61.72 111.79,62.49 U11.13
  BOTTOM w0.127: v1(109.72,61.21) 109.06,61.21 104.74,56.9 v1(87.85,56.9)
RMII0_MDIO: length 31.9
  TOP w0.127: v1(110.43,62.38) 110.43,63.28 U11.12 ; R8.2 88.21,55.92 88.09,55.92 v1(87.93,56.08) 87.62,56.08 86.45,57.25 U1.81
  BOTTOM w0.127: v1(110.43,62.38) 110.24,62.19 110.24,61 105.89,56.64 88.49,56.64 v1(87.93,56.08)
RMII0_RXD0: length 37.3
  TOP w0.127: R63.1 v1(105,68.07) ; U1.65 80.38,53.81 v1(80.46,53.9)
  BOTTOM w0.127: v1(105,68.07) 103.96,67.03 103.96,61.57 100.32,57.92 85.43,57.92 81.41,53.9 v1(80.46,53.9)
RMII0_RXD1: length 40.7
  TOP w0.127: U1.64 79.88,53.67 v1(79.62,53.92) ; R64.1 v1(105.07,70.84)
  BOTTOM w0.127: v1(105.07,70.84) 103.7,69.47 103.7,61.67 100.21,58.18 85.33,58.18 81.58,54.43 80.13,54.43 v1(79.62,53.92)
RMII0_RXER: length 45.4
  TOP w0.127: v1(75.38,52.43) 75.38,52.42 U1.55 ; R74.2 107.49,62.36 R70.1 v1(108.73,63.73) 109.93,64.93 U11.10
  BOTTOM w0.127: v1(108.73,63.73) 108.73,62.36 104.05,57.67 87.15,57.67 82.8,53.31 76.27,53.31 v1(75.38,52.43)
RMII0_TXD0: length 47.4
  TOP w0.127: v1(114.69,61.79) 113.79,62.69 U11.17 ; R2.1 v1(81.22,45.42)
  BOTTOM w0.127: v1(114.69,61.79) 114.69,54.93 107.17,47.41 83.22,47.41 v1(81.22,45.42)
RMII0_TXD1: length 47.5
  TOP w0.127: v1(115.6,61.71) 114.29,63.03 U11.18 ; R4.1 82.57,45.47 82.49,45.39 82.49,45.34 v1(82.47,45.31)
  BOTTOM w0.127: v1(115.6,61.71) 115.6,54.83 107.93,47.16 84.31,47.16 v1(82.47,45.31)
RMII0_TXEN: length 53.1
  TOP w0.127: U11.16 113.29,62.2 113.71,61.77 v1(113.92,61.77) ; v1(80.28,45.52) 80.28,48.79 81.38,49.89 U1.67
  BOTTOM w0.127: v1(80.28,45.52) 82.43,47.66 98.35,47.66 99.42,48.73 108.13,48.73 114.43,55.04 114.43,61.26 v1(113.92,61.77)
RS485_5V: length 21.4
  TOP w0.508: v1(66.03,132.38) 66.54,131.88 L16.2 ; C87.2 64.94,131.9 v1(64.51,132.33) ; v1(45.09,134.68) C88.1 47.2,133.53 U25.8 ; v1(28.26,134.09) 28.51,133.84 C85.1 29.01,133.66 U21.8 ; L17.2 v1(60.48,131.2) ; R104.1 v1(45.81,156.1) ; v1(50.62,121.01) 50.36,121.26 R130.1 ; R126.1 v1(49.84,137.14) ; R118.1 v1(32.81,120.57) ; R103.1 v1(57.98,155.85) ; R116.1 v1(32.26,136.44) ; v1(49.09,120.93) 48.74,121.28 R123.1 ; L15.2 v1(62.94,132.41) ; R114.1 v1(31.06,120.6)
RS485I_A: length 22.1
  TOP w0.508: U21.6 31.55,131.99 32.26,132.7 R116.2 33.36,133.75 ; 33.36,133.75 34.89,132.22 J12.2 ; 33.36,133.75 33.93,134.32 33.93,136.86 32.53,138.25 30.75,138.25 28.56,140.45 R122.1 24.74,141.23 TVS2.2
RS485I_B: length 31.5
  TOP w0.305: R124.2 23.63,133.28 15.69,141.22 TVS3.1 10.3,141.22 R128.1
  TOP w0.508: R124.2 26.98,130.06 27.81,129.24 29.89,129.24 30.28,129.63 U21.7 30.28,132.39 30.87,132.98 R117.2
RS485I_DIR: length 67
  TOP w0.127: R115.2 28.97,108.6 34.34,103.23 42.26,103.23 48.56,96.93 48.56,74.52 56.68,66.41 61.65,66.41 63.81,64.25 U1.14
RS485I_RX: length 97.4
  TOP w0.127: U19.4 24.33,109.71 R112.1 ; U1.46 70.88,66.36 65.5,71.74 65.5,99.09 v1(65.09,99.49)
  BOTTOM w0.127: U19.4 29.25,106.74 57.59,106.74 64.84,99.49 v1(65.09,99.49)
RS485I_TX: length 84.6
  TOP w0.127: v1(35.35,106.1) 35.16,106.28 R119.2 ; U1.45 70.38,66.5 65.25,71.63 65.25,98.2 v1(64.76,98.68)
  BOTTOM w0.127: v1(35.35,106.1) 57.35,106.1 v1(64.76,98.68)
RS485IA: length 18.3
  TOP w0.305: R122.2 30.49,142.91 29.41,143.99 29.41,143.99 V4.1 27.8,147.68 J13.2
RS485IB: length 17.8
  TOP w0.305: R128.2 8.26,149.58 V5.2 7.87,152.02 11.13,155.28 J13.4
RS485II_A: length 17.7
  TOP w0.508: U25.6 49.74,134.39 49.84,134.49 53.34,134.49 J14.2 56.62,137.78 R129.1 53.16,141.37 TVS4.2
RS485II_B: length 20.6
  TOP w0.508: U25.7 48.37,132.21 R127.2 47.66,134.53 47.24,134.95 47.24,136.93 46.88,137.29 44.85,137.29 44.44,136.88 44.44,135.97 44.33,135.85 R132.2 43.01,140.34 TVS5.1 38.64,141.41 R133.1
RS485II_DIR: length 70.7
  TOP w0.127: U1.13 63.81,64.75 61.9,66.66 56.78,66.66 48.81,74.63 48.81,97.69 39.52,106.98 39.52,111.46 40.18,112.12 43.56,112.12 45.28,110.39 45.28,108.74 45.96,108.06 R125.2
RS485II_RX: length 58.1
  TOP w0.127: U1.12 63.7,65.25 62.03,66.92 56.89,66.92 49.09,74.72 49.09,100.33 42.64,106.78 R120.1 42.64,109.07 43.22,109.65 U24.4
RS485II_TX: length 54.2
  TOP w0.127: R131.2 49.34,105.04 49.34,74.82 56.99,67.17 62.38,67.17 63.8,65.75 U1.11
RS485IIA: length 25.8
  TOP w0.305: J15.1 50.35,145.86 V6.1 58.55,144.81 R129.2
RS485IIB: length 16.9
  TOP w0.305: J15.3 37.67,151.54 V7.2 35.92,148.36 35.92,142.2 R133.2
RTC_XTALI: length 4.5
  TOP w0.127: C21.1 66.62,42.11 QZ1.2 67.77,43.81 68.32,43.27 R12.2
RTC_XTALO: length 11.8
  TOP w0.127: U1.40 67.88,47.57 QZ1.1 64.12,43.44 65.17,42.4 C20.1
RX232_RX1: length 7.3
  TOP w0.305: TP24.1 119.76,32.99 119.78,32.99 120.09,32.69 120.09,30.18 R141.2
RX232_TX1: length 6.2
  TOP w0.305: R137.2 120.81,32.89 120.81,34.36 TP23.1
SPI1_PCS0: length 111.9
  TOP w0.127: U5.1 89.58,142.37 v1(89.75,142.53) 89.97,142.76 R24.1 ; v1(77.54,144.84) 77.26,145.12 75.42,145.12 74.47,144.17 74.47,140.93 76.35,139.05 76.35,113.62 63.23,100.5 63.23,77.82 57.07,71.66 57.07,68.86 57.63,68.3 63.09,68.3 63.64,67.75 U1.7
  BOTTOM w0.127: v1(89.75,142.53) 89.15,143.13 79.24,143.13 77.54,144.83 v1(77.54,144.84)
SPI1_PCS2: length 114.2
  TOP w0.127: v1(77.46,145.6) 75.54,145.6 74.21,144.28 74.21,140.82 76.09,138.94 76.09,113.72 62.97,100.6 62.97,77.93 56.81,71.77 56.81,68.75 57.52,68.05 62.58,68.05 63.38,67.25 U1.8
  BOTTOM w0.127: v1(77.46,145.6) 78.34,145.6 79.85,144.09 82.34,144.09 90.1,151.85 J21.4
SPI1_SCK: length 94.9
  TOP w0.127: U5.6 v1(81.85,144.91) 82.21,144.55 82.21,141.31 76.86,135.95 76.86,113.41 63.74,100.29 63.74,77.61 58.8,72.67 58.8,71.56 R13.1
  BOTTOM w0.127: J21.8 81.85,148.99 v1(81.85,144.91)
SPI1_SIN: length 117.3
  TOP w0.127: U1.4 62.57,69.25 61.01,70.82 58.34,70.82 57.91,71.25 57.91,72.14 63.48,77.72 63.48,100.39 76.6,113.51 76.6,139.15 74.72,141.03 74.72,143.87 75.18,144.32 77.87,144.32 v1(78.35,144.81) ; J21.6 88.1,149.98 86.43,148.31 86.43,144.2 86.99,143.64 U5.2 v1(89.58,143.64)
  BOTTOM w0.127: v1(78.35,144.81) 79.52,143.64 v1(89.58,143.64)
SPI1_SOUT: length 96.2
  TOP w0.127: U1.2 62.66,70.25 62.12,70.79 62.12,75.64 63.99,77.5 63.99,100.18 77.11,113.3 77.11,135.84 82.7,141.43 82.7,145.47 81.98,146.18 U5.5 80.31,147.29 v1(80.41,147.4)
  BOTTOM w0.127: v1(80.41,147.4) 80.41,151.55 J21.12
SWD_CLK: length 72.9
  TOP w0.127: U1.50 72.88,20.3 80.48,12.7 106.18,12.7 108.81,10.08 J18.9
SWD_DIO: length 74.6
  TOP w0.127: U1.53 74.38,49.79 73.66,49.07 73.66,20.59 80.77,13.49 107.72,13.49 111.35,9.86 J18.7
U1P_IN: length 43.2
  TOP w0.305: R33.1 40.37,58.05 v1(40.94,57.48) 41.73,56.69 U6.6
  BOTTOM w0.305: PT1.4 34.54,87.87 34.54,63.88 v1(40.94,57.48)
U1P_OUT: length 40.6
  TOP w0.305: v1(64.84,52.4) 64.43,52.81 U1.36 ; v1(43.12,65.63) 40.89,65.63 38.72,63.46 R31.2 36.79,63.28 C39.1
  BOTTOM w0.305: v1(64.84,52.4) 66.6,54.16 66.6,56.51 65.18,57.94 53.61,57.94 53.59,57.91 51.63,57.91 43.91,65.63 v1(43.12,65.63)
U2_IN_L: length 38.8
  TOP w0.178: v1(34.65,53.29) 35.26,53.29 R43.1 36.46,54.5 C43.1 34.51,56.65 30.34,60.82 PT2.4 28.57,60.82 26.71,62.69 26.71,64.65 R42.1 26.76,64.7 D15.A ; v1(40.51,41.81) 40.51,42.78 41.22,43.49 R37.1
  BOTTOM w0.178: v1(40.51,41.81) 40.51,42.88 39.3,44.23 39.3,51.27 37.51,53.06 34.87,53.06 v1(34.65,53.29)
